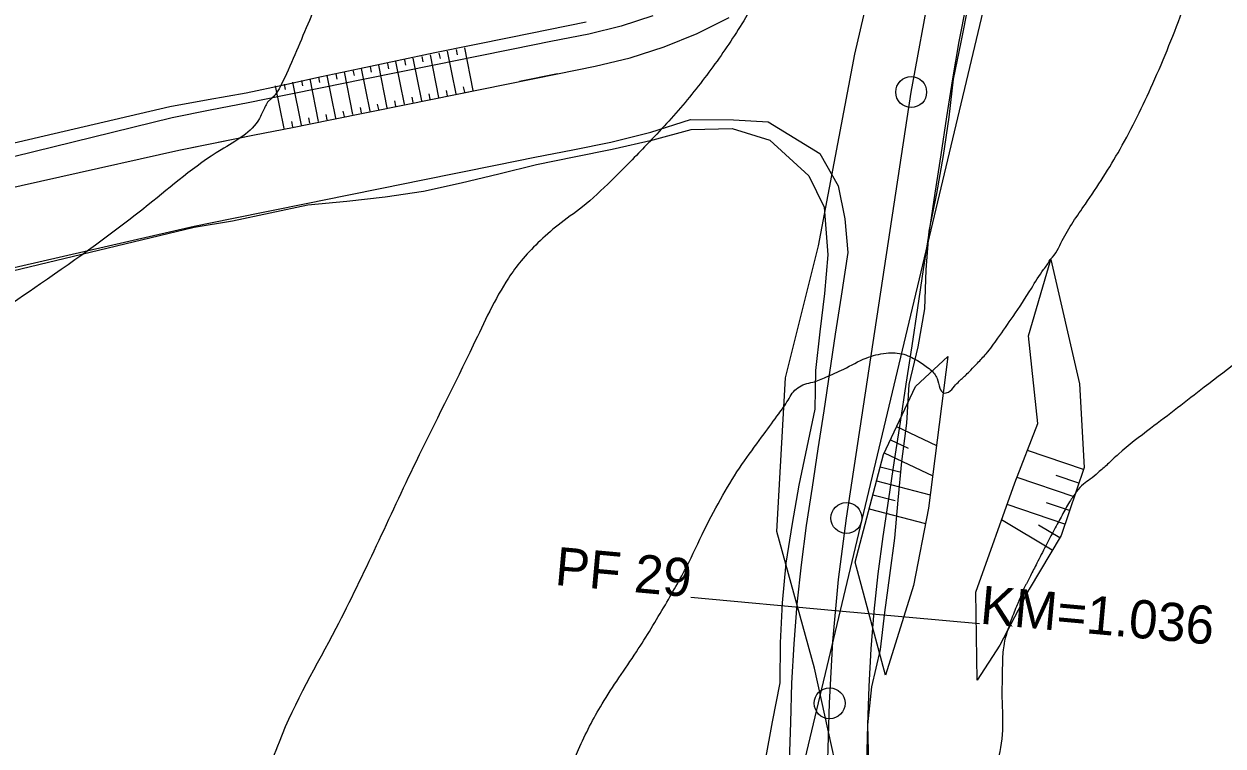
# Model space of a CAD drawing. Extents: x -475575 to -473225, y -1116053 to -1114104.
# Drawn here: x -474372 to -474309.9, y -1114513.7 to -1114476.4 of the extents above; entities that cross this region are included whole.
import ezdxf

# ---------------------------------------------------------------- set-up
doc = ezdxf.new("R2010")
doc.units = 0
for name, color, linetype in [('CESTN___P____KOP_N__VRH__Construction_', 7, 'Continuous'), ('cesty', 7, 'Continuous'), ('hrana_P', 7, 'Continuous'), ('plyn_vtl', 7, 'Continuous'), ('POLYGONY_SITUACE_PF', 7, 'Continuous'), ('POLYGONY_SITUACE_PF_POPISY', 7, 'Continuous'), ('POLYGONY_SITUACE_PO', 7, 'Continuous'), ('Vrstevnice_hlavni', 7, 'Continuous'), ('Vrstevnice_vedlejsi', 7, 'Continuous'), ('Vrstva_10', 7, 'Continuous')]:
    doc.layers.add(name, color=color, linetype=linetype)

msp = doc.modelspace()

# ---------------------------------------------------------------- linework, layer by layer
at = {"layer": 'CESTN___P____KOP_N__VRH__Construction_'}
for p, q in [((-474323.228, -1114475.348), (-474323.604, -1114477.269)), ((-474323.483, -1114477.292), (-474323.104, -1114475.374)), ((-474323.604, -1114477.269), (-474323.94, -1114479.198)), ((-474323.885, -1114479.207), (-474323.483, -1114477.292)), ((-474323.94, -1114479.198), (-474324.242, -1114481.154)), ((-474324.099, -1114481.175), (-474323.885, -1114479.207)), ((-474324.242, -1114481.154), (-474324.543, -1114483.131)), ((-474337.499, -1114481.302), (-474337.499, -1114481.302)), ((-474337.499, -1114481.302), (-474335.27, -1114481.307)), ((-474335.27, -1114481.307), (-474333.469, -1114481.42)), ((-474333.469, -1114481.42), (-474330.804, -1114483.059)), ((-474324.392, -1114483.154), (-474324.099, -1114481.175)), ((-474330.804, -1114483.059), (-474329.855, -1114484.736)), ((-474324.543, -1114483.131), (-474324.844, -1114485.108)), ((-474324.747, -1114485.123), (-474324.392, -1114483.154)), ((-474329.855, -1114484.736), (-474329.502, -1114486.432)), ((-474324.844, -1114485.108), (-474325.144, -1114487.085)), ((-474325.142, -1114487.086), (-474324.747, -1114485.123)), ((-474329.502, -1114486.432), (-474329.357, -1114488.18)), ((-474325.144, -1114487.085), (-474325.445, -1114489.063)), ((-474325.298, -1114489.085), (-474325.142, -1114487.086)), ((-474329.357, -1114488.18), (-474329.7, -1114490.438)), ((-474325.445, -1114489.063), (-474325.746, -1114491.04)), ((-474325.371, -1114491.097), (-474325.298, -1114489.085)), ((-474329.7, -1114490.438), (-474330.001, -1114492.416)), ((-474325.746, -1114491.04), (-474326.047, -1114493.017)), ((-474325.712, -1114493.068), (-474325.371, -1114491.097)), ((-474330.001, -1114492.416), (-474330.302, -1114494.393)), ((-474326.047, -1114493.017), (-474326.347, -1114494.994)), ((-474326.178, -1114495.02), (-474325.712, -1114493.068)), ((-474330.302, -1114494.393), (-474330.603, -1114496.37)), ((-474326.347, -1114494.994), (-474326.648, -1114496.972)), ((-474326.304, -1114497.024), (-474326.178, -1114495.02)), ((-474330.603, -1114496.37), (-474330.903, -1114498.347)), ((-474326.648, -1114496.972), (-474326.949, -1114498.949)), ((-474326.563, -1114499.007), (-474326.304, -1114497.024)), ((-474330.903, -1114498.347), (-474331.204, -1114500.325)), ((-474326.949, -1114498.949), (-474327.25, -1114500.926)), ((-474326.747, -1114501.002), (-474326.563, -1114499.007)), ((-474331.204, -1114500.325), (-474331.504, -1114502.319)), ((-474327.25, -1114500.926), (-474327.545, -1114502.887)), ((-474326.916, -1114502.977), (-474326.747, -1114501.002)), ((-474331.504, -1114502.319), (-474331.77, -1114504.352)), ((-474327.545, -1114502.887), (-474327.797, -1114504.82)), ((-474327.185, -1114504.893), (-474326.916, -1114502.977)), ((-474331.77, -1114504.352), (-474331.985, -1114506.391)), ((-474327.797, -1114504.82), (-474328.002, -1114506.76)), ((-474327.439, -1114506.812), (-474327.185, -1114504.893)), ((-474331.985, -1114506.391), (-474332.148, -1114508.434)), ((-474328.002, -1114506.76), (-474328.157, -1114508.703)), ((-474327.661, -1114508.737), (-474327.439, -1114506.812)), ((-474332.148, -1114508.434), (-474332.261, -1114510.481)), ((-474328.157, -1114508.703), (-474328.264, -1114510.65)), ((-474328.113, -1114510.657), (-474327.661, -1114508.737)), ((-474332.261, -1114510.481), (-474332.328, -1114512.504)), ((-474328.264, -1114510.65), (-474328.33, -1114512.626)), ((-474328.323, -1114512.626), (-474328.113, -1114510.657)), ((-474332.328, -1114512.504), (-474332.389, -1114514.503)), ((-474328.33, -1114512.626), (-474328.391, -1114514.625)), ((-474328.267, -1114514.628), (-474328.323, -1114512.626))]:
    msp.add_line(p, q, dxfattribs=at)
for points in [[(-474330.392, -1114488.31), (-474330.568, -1114490.306)], [(-474330.392, -1114488.31), (-474330.392, -1114488.31)], [(-474330.568, -1114490.306), (-474330.795, -1114492.295)], [(-474330.795, -1114492.295), (-474331.021, -1114494.283)], [(-474331.021, -1114494.283), (-474331.069, -1114496.299)], [(-474331.069, -1114496.299), (-474331.481, -1114498.26)], [(-474331.481, -1114498.26), (-474331.894, -1114500.22)], [(-474331.894, -1114500.22), (-474332.23, -1114502.215)], [(-474332.23, -1114502.215), (-474332.555, -1114504.259)], [(-474332.555, -1114504.259), (-474332.752, -1114506.32)], [(-474332.752, -1114506.32), (-474332.856, -1114508.386)], [(-474332.856, -1114508.386), (-474332.881, -1114510.455)], [(-474332.881, -1114510.455), (-474333.276, -1114512.475)], [(-474333.276, -1114512.475), (-474333.627, -1114514.465)]]:
    msp.add_lwpolyline(points, dxfattribs=at)
at = {"layer": 'cesty'}
for p, q in [((-474337.149, -1114476.846), (-474335.49, -1114476.025)), ((-474346.807, -1114477.041), (-474344.847, -1114476.643)), ((-474344.847, -1114476.643), (-474342.894, -1114476.241)), ((-474348.768, -1114477.435), (-474346.807, -1114477.041)), ((-474338.865, -1114477.542), (-474337.149, -1114476.846)), ((-474352.687, -1114478.239), (-474350.727, -1114477.837)), ((-474350.727, -1114477.837), (-474348.768, -1114477.435)), ((-474340.627, -1114478.109), (-474338.865, -1114477.542)), ((-474356.599, -1114479.072), (-474354.643, -1114478.654)), ((-474354.643, -1114478.654), (-474352.687, -1114478.239)), ((-474344.385, -1114478.939), (-474342.427, -1114478.544)), ((-474342.427, -1114478.544), (-474340.627, -1114478.109)), ((-474358.553, -1114479.499), (-474356.599, -1114479.072)), ((-474348.306, -1114479.729), (-474344.385, -1114478.939)), ((-474362.479, -1114480.265), (-474360.51, -1114479.912)), ((-474360.51, -1114479.912), (-474358.553, -1114479.499)), ((-474352.227, -1114480.519), (-474348.306, -1114479.729)), ((-474364.447, -1114480.627), (-474362.479, -1114480.265)), ((-474356.148, -1114481.309), (-474352.227, -1114480.519)), ((-474360.07, -1114482.099), (-474358.109, -1114481.704)), ((-474358.109, -1114481.704), (-474356.148, -1114481.309)), ((-474337.458, -1114481.813), (-474335.336, -1114481.757)), ((-474335.336, -1114481.757), (-474333.396, -1114482.375)), ((-474362.03, -1114482.494), (-474360.07, -1114482.099)), ((-474341.558, -1114482.828), (-474339.434, -1114482.352)), ((-474339.434, -1114482.352), (-474337.458, -1114481.813)), ((-474333.396, -1114482.375), (-474331.364, -1114484.217)), ((-474363.991, -1114482.889), (-474362.03, -1114482.494)), ((-474343.521, -1114483.226), (-474341.558, -1114482.828)), ((-474347.424, -1114484.104), (-474345.479, -1114483.634)), ((-474345.479, -1114483.634), (-474343.521, -1114483.226)), ((-474349.371, -1114484.57), (-474347.424, -1114484.104)), ((-474331.364, -1114484.217), (-474330.573, -1114485.835)), ((-474351.324, -1114485.003), (-474349.371, -1114484.57)), ((-474355.298, -1114485.528), (-474353.303, -1114485.307)), ((-474353.303, -1114485.307), (-474351.324, -1114485.003)), ((-474359.258, -1114486.127), (-474357.302, -1114485.709)), ((-474357.302, -1114485.709), (-474355.298, -1114485.528)), ((-474330.573, -1114485.835), (-474330.392, -1114488.31)), ((-474363.188, -1114486.873), (-474361.215, -1114486.54)), ((-474361.215, -1114486.54), (-474359.258, -1114486.127))]:
    msp.add_line(p, q, dxfattribs=at)
for points in [[(-474339.447, -1114475.939), (-474341.089, -1114476.467)], [(-474341.089, -1114476.467), (-474342.766, -1114476.873)], [(-474344.722, -1114477.267), (-474346.682, -1114477.662)], [(-474342.766, -1114476.873), (-474344.722, -1114477.267)], [(-474351.412, -1114478.035), (-474351.357, -1114478.311)], [(-474350.524, -1114480.154), (-474350.967, -1114477.946)], [(-474350.522, -1114477.857), (-474350.467, -1114478.133)], [(-474349.634, -1114479.976), (-474350.077, -1114477.767)], [(-474349.632, -1114477.678), (-474349.577, -1114477.954)], [(-474348.744, -1114479.797), (-474349.187, -1114477.589)], [(-474346.682, -1114477.662), (-474348.643, -1114478.057)], [(-474354.085, -1114480.868), (-474354.528, -1114478.66)], [(-474354.083, -1114478.571), (-474354.027, -1114478.847)], [(-474353.195, -1114480.69), (-474353.638, -1114478.482)], [(-474353.193, -1114478.392), (-474353.137, -1114478.668)], [(-474352.305, -1114480.511), (-474352.748, -1114478.303)], [(-474350.604, -1114478.452), (-474352.564, -1114478.847)], [(-474352.302, -1114478.214), (-474352.247, -1114478.49)], [(-474351.414, -1114480.333), (-474351.857, -1114478.124)], [(-474348.643, -1114478.057), (-474350.604, -1114478.452)], [(-474357.643, -1114479.285), (-474357.588, -1114479.561)], [(-474356.755, -1114481.404), (-474357.198, -1114479.196)], [(-474356.753, -1114479.106), (-474356.698, -1114479.383)], [(-474354.525, -1114479.242), (-474356.485, -1114479.637)], [(-474355.865, -1114481.225), (-474356.308, -1114479.017)], [(-474355.863, -1114478.928), (-474355.808, -1114479.204)], [(-474354.975, -1114481.047), (-474355.418, -1114478.839)], [(-474354.973, -1114478.749), (-474354.917, -1114479.025)], [(-474352.564, -1114478.847), (-474354.525, -1114479.242)], [(-474358.535, -1114481.761), (-474358.978, -1114479.553)], [(-474358.533, -1114479.464), (-474358.478, -1114479.74)], [(-474356.485, -1114479.637), (-474358.446, -1114480.032)], [(-474357.645, -1114481.583), (-474358.088, -1114479.374)], [(-474350.079, -1114480.065), (-474350.135, -1114479.789)], [(-474349.189, -1114479.886), (-474349.245, -1114479.61)], [(-474360.406, -1114480.427), (-474362.367, -1114480.822)], [(-474358.446, -1114480.032), (-474360.406, -1114480.427)], [(-474353.64, -1114480.779), (-474353.695, -1114480.503)], [(-474352.75, -1114480.601), (-474352.805, -1114480.325)], [(-474351.86, -1114480.422), (-474351.915, -1114480.146)], [(-474350.969, -1114480.243), (-474351.025, -1114479.967)], [(-474390.512, -1114487.196), (-474383.244, -1114485.001), (-474364.447, -1114480.627)], [(-474362.367, -1114480.822), (-474364.328, -1114481.217)], [(-474356.31, -1114481.315), (-474356.365, -1114481.039)], [(-474355.42, -1114481.136), (-474355.475, -1114480.86)], [(-474354.53, -1114480.958), (-474354.585, -1114480.682)], [(-474364.328, -1114481.217), (-474382.81, -1114485.746), (-474390.148, -1114487.802)], [(-474358.09, -1114481.672), (-474358.146, -1114481.396)], [(-474357.2, -1114481.493), (-474357.256, -1114481.217)], [(-474339.544, -1114481.96), (-474337.499, -1114481.302)], [(-474341.631, -1114482.465), (-474339.544, -1114481.96)], [(-474399.057, -1114492.066), (-474382.495, -1114487.023), (-474363.991, -1114482.889)], [(-474345.555, -1114483.255), (-474343.595, -1114482.86)], [(-474343.595, -1114482.86), (-474341.631, -1114482.465)], [(-474347.516, -1114483.65), (-474345.555, -1114483.255)], [(-474351.437, -1114484.44), (-474349.476, -1114484.045)], [(-474349.476, -1114484.045), (-474347.516, -1114483.65)], [(-474355.358, -1114485.23), (-474353.398, -1114484.835)], [(-474353.398, -1114484.835), (-474351.437, -1114484.44)], [(-474357.319, -1114485.625), (-474355.358, -1114485.23)], [(-474361.24, -1114486.416), (-474359.279, -1114486.021)], [(-474359.279, -1114486.021), (-474357.319, -1114485.625)], [(-474363.201, -1114486.811), (-474361.24, -1114486.416)], [(-474397.715, -1114495.834), (-474381.185, -1114490.938), (-474363.201, -1114486.811)], [(-474397.609, -1114496.132), (-474381.095, -1114491.169), (-474363.188, -1114486.873)]]:
    msp.add_lwpolyline(points, dxfattribs=at)
at = {"layer": 'hrana_P'}
for points in [[(-474344.385, -1114478.939), (-474346.345, -1114479.334)], [(-474350.267, -1114480.124), (-474348.306, -1114479.729)], [(-474363.991, -1114482.889), (-474360.07, -1114482.099)]]:
    msp.add_lwpolyline(points, dxfattribs=at)
at = {"layer": 'plyn_vtl'}
msp.add_lwpolyline([(-473893.85, -1115442.85), (-473929.25, -1115381.23), (-473943.51, -1115301.92), (-473956.73, -1115230.35), (-474001.25, -1114984.78), (-474114.18, -1115020.15), (-474129.06, -1115005.44), (-474145.28, -1114973.47), (-474178.51, -1114909.8), (-474211.245, -1114846.864), (-474224.512, -1114820.325), (-474259.402, -1114751.636), (-474294.45, -1114683.77), (-474305.29, -1114617.92), (-474310.39, -1114567.14), (-474330.4, -1114528.44), (-474333.48, -1114522.48), (-474321.9, -1114473.82), (-474313.429, -1114443.805)], dxfattribs=at)
at = {"layer": 'POLYGONY_SITUACE_PF'}
msp.add_lwpolyline([(-474337.474, -1114506.029), (-474330.005, -1114506.708), (-474322.536, -1114507.388)], dxfattribs=at)
at = {"layer": 'POLYGONY_SITUACE_PO'}
msp.add_lwpolyline([(-474312.151, -1114577.459), (-474328.009, -1114537.047), (-474329.229, -1114533.406), (-474330.076, -1114529.66), (-474330.54, -1114525.847), (-474330.617, -1114522.007), (-474330.297, -1114511.516), (-474330.135, -1114508.309), (-474329.844, -1114505.111), (-474329.425, -1114501.927), (-474326.072, -1114479.879), (-474325.062, -1114474.35), (-474323.728, -1114468.889), (-474322.073, -1114463.517), (-474317.123, -1114448.995)], dxfattribs=at)
for centre in [(-474326.072, -1114479.879), (-474329.425, -1114501.927), (-474330.297, -1114511.516)]:
    msp.add_circle(centre, 0.8, dxfattribs=at)
at = {"layer": 'Vrstevnice_hlavni'}
msp.add_spline([(-474314.465, -1114423.562), (-474315.15, -1114426.169), (-474316.163, -1114431.774), (-474317.369, -1114436.945), (-474318.766, -1114441.68), (-474320.354, -1114445.981), (-474321.972, -1114449.681), (-474323.617, -1114452.78), (-474325.291, -1114455.277), (-474326.741, -1114457.93), (-474327.967, -1114460.736), (-474328.969, -1114463.698), (-474329.844, -1114466.14), (-474330.593, -1114468.063), (-474331.215, -1114469.466), (-474332.084, -1114471.237), (-474333.198, -1114473.375), (-474334.559, -1114475.88), (-474336.125, -1114478.272), (-474337.896, -1114480.55), (-474339.872, -1114482.714), (-474341.606, -1114484.471), (-474343.097, -1114485.82), (-474344.345, -1114486.761), (-474345.399, -1114487.69), (-474346.258, -1114488.605), (-474346.922, -1114489.508), (-474348.744, -1114492.982), (-474351.724, -1114499.027), (-474355.862, -1114507.643), (-474358.802, -1114513.52), (-474360.543, -1114516.658), (-474361.086, -1114517.057), (-474361.549, -1114517.367), (-474361.932, -1114517.589), (-474362.234, -1114517.723), (-474362.692, -1114518.027), (-474363.306, -1114518.501), (-474364.075, -1114519.145), (-474364.359, -1114519.998), (-474364.157, -1114521.059), (-474363.469, -1114522.329), (-474364.041, -1114525.543), (-474365.872, -1114530.7), (-474368.962, -1114537.801), (-474371.03, -1114542.537), (-474372.077, -1114544.908), (-474372.101, -1114544.915), (-474372.13, -1114544.928), (-474372.164, -1114544.948), (-474372.202, -1114544.975), (-474373.035, -1114545.505), (-474374.661, -1114546.538), (-474377.082, -1114548.074), (-474379.165, -1114549.699), (-474380.91, -1114551.414), (-474382.317, -1114553.219), (-474383.093, -1114555.278), (-474383.239, -1114557.591), (-474382.271, -1114562.728)], degree=3, dxfattribs=at)
at = {"layer": 'Vrstevnice_vedlejsi'}
for points in [[(-474327.641, -1114407.394), (-474328.603, -1114410.163), (-474331.498, -1114418.235), (-474335.644, -1114429.118), (-474339.003, -1114437.261), (-474341.575, -1114442.664), (-474343.361, -1114445.328), (-474344.701, -1114447.548), (-474345.596, -1114449.324), (-474346.047, -1114450.656), (-474347.707, -1114454.61), (-474350.577, -1114461.188), (-474354.656, -1114470.389), (-474357.396, -1114476.561), (-474358.797, -1114479.703), (-474358.858, -1114479.815), (-474358.928, -1114479.922), (-474359.008, -1114480.025), (-474359.096, -1114480.122), (-474359.174, -1114480.201), (-474359.241, -1114480.261), (-474359.297, -1114480.304), (-474359.345, -1114480.345), (-474359.383, -1114480.386), (-474359.413, -1114480.427), (-474359.495, -1114480.583), (-474359.629, -1114480.854), (-474359.814, -1114481.241), (-474361.795, -1114482.862), (-474365.571, -1114485.716), (-474371.143, -1114489.805), (-474375.891, -1114492.988), (-474379.817, -1114495.267), (-474382.92, -1114496.64), (-474386.819, -1114499.089), (-474391.515, -1114502.613), (-474397.008, -1114507.212), (-474401.449, -1114508.322), (-474404.838, -1114505.943), (-474407.175, -1114500.076), (-474409.173, -1114494.493), (-474410.831, -1114489.194), (-474412.149, -1114484.18), (-474412.82, -1114480.198), (-474412.846, -1114477.248), (-474412.226, -1114475.331), (-474411.8, -1114474.019), (-474411.568, -1114473.315), (-474411.531, -1114473.216), (-474411.527, -1114473.077), (-474411.557, -1114472.897), (-474411.62, -1114472.676), (-474411.726, -1114472.437), (-474411.876, -1114472.179), (-474412.069, -1114471.903), (-474414.084, -1114468.235), (-474417.923, -1114461.176), (-474423.583, -1114450.725), (-474427.711, -1114443.268), (-474430.305, -1114438.804), (-474431.366, -1114437.334), (-474432.27, -1114436.107), (-474433.015, -1114435.123), (-474433.603, -1114434.383), (-474434.851, -1114432.753), (-474436.762, -1114430.233)], [(-474355.556, -1114543.361), (-474352.458, -1114539.678), (-474350.201, -1114536.503), (-474348.784, -1114533.835), (-474348.208, -1114531.674), (-474347.44, -1114529.095), (-474346.48, -1114526.098), (-474345.329, -1114522.683), (-474344.527, -1114519.848), (-474344.072, -1114517.594), (-474343.965, -1114515.921), (-474343.3, -1114513.907), (-474342.078, -1114511.551), (-474340.298, -1114508.855), (-474338.801, -1114506.412), (-474337.589, -1114504.223), (-474336.659, -1114502.288), (-474335.699, -1114500.535), (-474334.708, -1114498.964), (-474333.686, -1114497.575), (-474332.932, -1114496.529), (-474332.448, -1114495.826), (-474332.232, -1114495.464), (-474331.945, -1114495.189), (-474331.587, -1114494.998), (-474331.157, -1114494.893), (-474330.483, -1114494.633), (-474329.567, -1114494.218), (-474328.408, -1114493.648), (-474327.37, -1114493.393), (-474326.453, -1114493.453), (-474325.658, -1114493.828), (-474325.081, -1114494.246), (-474324.724, -1114494.708), (-474324.587, -1114495.213), (-474324.393, -1114495.446), (-474324.142, -1114495.407), (-474323.836, -1114495.095), (-474323.582, -1114494.843), (-474323.379, -1114494.649), (-474323.23, -1114494.514), (-474322.982, -1114494.265), (-474322.637, -1114493.902), (-474322.193, -1114493.424), (-474321.581, -1114492.621), (-474320.8, -1114491.493), (-474319.849, -1114490.041), (-474319.214, -1114489.066), (-474318.892, -1114488.571), (-474318.885, -1114488.553), (-474318.878, -1114488.539), (-474318.869, -1114488.528), (-474318.859, -1114488.519), (-474318.255, -1114487.568), (-474317.055, -1114485.674), (-474315.26, -1114482.837), (-474313.562, -1114479.439), (-474311.96, -1114475.48), (-474310.456, -1114470.96), (-474308.985, -1114466.231), (-474307.548, -1114461.294), (-474306.145, -1114456.148), (-474304.72, -1114450.879), (-474303.271, -1114445.486), (-474301.8, -1114439.969), (-474301.619, -1114439.327)], [(-474285.584, -1114455.09), (-474287.861, -1114463.438), (-474290.127, -1114471.624), (-474291.545, -1114476.573), (-474292.115, -1114478.287), (-474292.723, -1114479.789), (-474293.369, -1114481.08), (-474294.052, -1114482.159), (-474295.443, -1114483.552), (-474297.544, -1114485.257), (-474300.353, -1114487.276), (-474303.516, -1114489.599), (-474307.035, -1114492.227), (-474310.908, -1114495.161), (-474313.678, -1114497.291), (-474315.344, -1114498.619), (-474315.906, -1114499.145), (-474316.394, -1114499.578), (-474316.809, -1114499.918), (-474317.151, -1114500.165), (-474317.506, -1114500.558), (-474317.875, -1114501.096), (-474318.259, -1114501.779), (-474318.669, -1114502.535), (-474319.105, -1114503.365), (-474319.567, -1114504.268), (-474319.903, -1114504.922), (-474320.11, -1114505.325), (-474320.191, -1114505.478), (-474320.349, -1114505.842), (-474320.583, -1114506.416), (-474320.895, -1114507.201), (-474321.122, -1114507.87), (-474321.264, -1114508.425), (-474321.321, -1114508.865), (-474321.357, -1114509.797), (-474321.371, -1114511.221), (-474321.363, -1114513.138), (-474321.709, -1114514.887), (-474322.409, -1114516.468), (-474323.464, -1114517.88), (-474324.278, -1114519.633), (-474324.852, -1114521.728), (-474325.186, -1114524.165), (-474325.75, -1114526.308), (-474326.546, -1114528.159), (-474327.572, -1114529.717), (-474328.814, -1114531.46), (-474330.273, -1114533.386), (-474331.949, -1114535.496), (-474333.023, -1114537.404), (-474333.496, -1114539.107), (-474333.369, -1114540.608), (-474333.308, -1114542.517), (-474333.316, -1114544.833), (-474333.39, -1114547.558), (-474334.649, -1114550.83), (-474337.09, -1114554.649), (-474340.715, -1114559.015), (-474344.384, -1114565.016), (-474348.097, -1114572.652), (-474351.854, -1114581.923), (-474354.717, -1114588.652), (-474356.687, -1114592.838), (-474357.764, -1114594.482), (-474358.075, -1114595.992), (-474357.62, -1114597.368), (-474356.4, -1114598.611), (-474355.953, -1114600.167), (-474356.279, -1114602.036), (-474357.378, -1114604.218), (-474358.428, -1114605.971), (-474359.43, -1114607.294), (-474360.384, -1114608.189), (-474361.122, -1114609.089), (-474361.645, -1114609.996)], [(-474370.242, -1114755.46), (-474370.143, -1114754.388), (-474370.03, -1114753.444), (-474369.902, -1114752.628), (-474369.758, -1114751.941), (-474369.779, -1114750.9), (-474369.965, -1114749.506), (-474370.315, -1114747.759), (-474370.588, -1114746.346), (-474370.784, -1114745.267), (-474370.904, -1114744.521), (-474371.032, -1114743.681), (-474371.167, -1114742.747), (-474371.311, -1114741.719), (-474371.285, -1114740.759), (-474371.089, -1114739.865), (-474370.724, -1114739.039), (-474370.319, -1114738.151), (-474369.874, -1114737.2), (-474369.39, -1114736.187), (-474368.449, -1114734.378), (-474367.052, -1114731.774), (-474365.198, -1114728.373), (-474363.769, -1114725.694), (-474362.765, -1114723.736), (-474362.187, -1114722.499), (-474361.701, -1114721.187), (-474361.307, -1114719.8), (-474361.004, -1114718.337), (-474360.699, -1114717.01), (-474360.391, -1114715.817), (-474360.08, -1114714.758), (-474358.924, -1114712.244), (-474356.924, -1114708.275), (-474354.079, -1114702.85), (-474351.398, -1114698.199), (-474348.882, -1114694.319), (-474346.53, -1114691.213), (-474344.569, -1114688.436), (-474343, -1114685.987), (-474341.823, -1114683.867), (-474340.569, -1114681.752), (-474339.238, -1114679.641), (-474337.831, -1114677.534), (-474335.985, -1114672.859), (-474333.701, -1114665.616), (-474330.979, -1114655.805), (-474329.274, -1114649.012), (-474328.587, -1114645.238), (-474328.919, -1114644.483), (-474329.063, -1114643.578), (-474329.019, -1114642.525), (-474328.788, -1114641.322), (-474328.335, -1114639.8), (-474327.66, -1114637.959), (-474326.762, -1114635.799), (-474325.513, -1114632.736), (-474323.91, -1114628.771), (-474321.955, -1114623.904), (-474320.056, -1114619.053), (-474318.212, -1114614.216), (-474316.424, -1114609.395), (-474315.076, -1114605.754), (-474314.17, -1114603.291), (-474313.705, -1114602.008), (-474313.056, -1114599.982), (-474312.224, -1114597.214), (-474311.208, -1114593.704), (-474309.119, -1114588.008), (-474305.955, -1114580.129), (-474301.718, -1114570.064), (-474298.467, -1114561.838), (-474296.203, -1114555.45), (-474294.926, -1114550.901), (-474293.186, -1114544.94), (-474290.982, -1114537.567), (-474288.316, -1114528.784), (-474286.496, -1114522.666), (-474285.522, -1114519.213), (-474285.395, -1114518.427), (-474285.261, -1114517.866), (-474285.118, -1114517.531), (-474284.969, -1114517.423), (-474284.333, -1114516.85), (-474283.212, -1114515.813), (-474281.606, -1114514.311), (-474276.141, -1114509.715), (-474266.818, -1114502.025), (-474253.636, -1114491.24), (-474249.353, -1114487.74)]]:
    msp.add_spline(points, degree=3, dxfattribs=at)
at = {"layer": 'Vrstva_10'}
for p, q in [((-474326.825, -1114497.196), (-474324.759, -1114498.172)), ((-474327.145, -1114497.874), (-474326.23, -1114498.306)), ((-474317.151, -1114499.408), (-474320.046, -1114498.424)), ((-474327.465, -1114498.552), (-474324.956, -1114499.737)), ((-474327.674, -1114499.271), (-474326.599, -1114499.553)), ((-474317.392, -1114500.118), (-474318.562, -1114499.72)), ((-474327.865, -1114499.996), (-474325.081, -1114500.728)), ((-474317.633, -1114500.828), (-474320.59, -1114499.824)), ((-474328.056, -1114500.721), (-474326.905, -1114501.024)), ((-474328.247, -1114501.446), (-474325.325, -1114502.215)), ((-474318.115, -1114502.249), (-474321.104, -1114501.233)), ((-474317.874, -1114501.538), (-474319.065, -1114501.134)), ((-474318.765, -1114503.592), (-474321.389, -1114502.028)), ((-474318.381, -1114502.947), (-474319.481, -1114502.292))]:
    msp.add_line(p, q, dxfattribs=at)
for points in [[(-474333.027, -1114502.62), (-474332.577, -1114494.663), (-474330.866, -1114487.83), (-474328.997, -1114477.921), (-474326.996, -1114469.3), (-474323.692, -1114459.536), (-474310.981, -1114431.627)], [(-474322.65, -1114510.327), (-474322.727, -1114505.762), (-474320.701, -1114500.109), (-474319.507, -1114497.037), (-474319.994, -1114492.498), (-474318.846, -1114488.538)], [(-474318.846, -1114488.538), (-474317.351, -1114494.988), (-474317.117, -1114499.309), (-474318.315, -1114502.836), (-474319.971, -1114505.615), (-474321.481, -1114508.512), (-474322.65, -1114510.327)], [(-474327.405, -1114510.062), (-474328.974, -1114504.211), (-474327.51, -1114498.646), (-474325.843, -1114495.118), (-474324.177, -1114493.564)], [(-474324.177, -1114493.564), (-474325.169, -1114501.424), (-474325.958, -1114505.427), (-474327.405, -1114510.062)], [(-474427.598, -1114573.213), (-474427.733, -1114562.104), (-474424.523, -1114559.79), (-474413.059, -1114556.599), (-474404.738, -1114552.841), (-474396.454, -1114549.688), (-474390.919, -1114543.238), (-474386.29, -1114544.085), (-474377.593, -1114542.759), (-474371.98, -1114544.93), (-474366.567, -1114548.459), (-474359.955, -1114547.613), (-474345.759, -1114541.411), (-474335.865, -1114538.563), (-474329.008, -1114535.638), (-474328.493, -1114530.157), (-474329.129, -1114518.57), (-474331.081, -1114509.695), (-474333.027, -1114502.62)]]:
    msp.add_lwpolyline(points, dxfattribs=at)

# ---------------------------------------------------------------- texts
at = {"layer": 'POLYGONY_SITUACE_PF_POPISY'}
for s, p in [('PF 29', (-474344.561, -1114505.384)), ('KM=1.036', (-474322.548, -1114507.387))]:
    msp.add_text(s, height=1.9765, rotation=354.80238, dxfattribs=at).set_placement(p)

doc.saveas('drawing.dxf')
